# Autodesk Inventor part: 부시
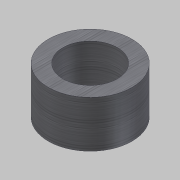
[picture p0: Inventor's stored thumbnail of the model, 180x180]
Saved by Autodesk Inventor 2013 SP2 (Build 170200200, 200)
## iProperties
Company: 한국ATC센터
Created: 2014-10
Part Number: 부시
Document SubType Name: Modeling
Designer: 한국ATC센터
Density: 7.86 g/cm^3
Material: 강, 연강
Mass: 157.788 g
Surface Area: 70.2617 cm^2
Volume: 20.0748 cm^3
Author: KYOUNG IL JANG
Revision Number: 1
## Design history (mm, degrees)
sketch "스케치1"
  geometry: C1 r 21.5 at (0, 0) reference; C2 r 31 at (0, 0) reference; C3 r 14 at (0, 0) reference; 1 further point
  node "참조1"
  node "참조2"
node "작업 평면1"
extrude "돌출1" new body sketch "스케치1" stored distance "d0" = 10; taper "d1" = 0 deg
node "솔리드1"
